Omron CX-Programmer project NewProject (CX-Programmer 9.11)

# PLC NewPLC1: CP1L M

## Global symbols (name address type ; comment)
AbsoluteActualPosition D0 DINT  ; Absolute Actual Position
ActualVelocity D2 DINT  ; Actual Velocity
A641.00 BOOL  ; $?St$Bk?_#[4] / Modbus-RTU Master Execution Bit / Turned ON: Execution Started / ON: Execution In Progress / OFF: Not Executed Or Execution completed.$?St$Bk?_#[4]
A641.01 BOOL  ; $?St$Bk?_#[5] / Modbus-RTU Master Execution Normal Flag / ON: Execution Normal / OFF: Execution Error Or Still In Progress$?St$Bk?_#[5]
A641.02 BOOL  ; $?St$Bk?_#[6] / Modbus-RTU Master Execution Error Flag / ON: Execution Error / OFF: Execution Normal Or Still In Progress$?St$Bk?_#[6]
D100 CHANNEL  ; Number Of Modbus Data Bytes
H0 CHANNEL  ; Input Status
H0.00 BOOL  ; Input 1
H0.01 BOOL  ; Input 2
H0.02 BOOL  ; Input 3
H0.03 BOOL  ; Input 4
H0.04 BOOL  ; Input 5
H0.05 BOOL  ; Input 6
H0.06 BOOL  ; Input 7
H0.07 BOOL  ; Input 8
H1 CHANNEL  ; Input Status
H10 CHANNEL  ; Output Status
H10.00 BOOL  ; Output 1
H10.01 BOOL  ; Output 2
H10.02 BOOL  ; Output 3
H10.03 BOOL  ; Output 4
H10.04 BOOL  ; Output 5
H10.05 BOOL  ; Output 6
H10.06 BOOL  ; Output 7
H10.07 BOOL  ; Output 8
H11 CHANNEL  ; Output Status
H11.08 BOOL  ; Output 9
H11.09 BOOL  ; Output 10
H11.10 BOOL  ; Output 11
H11.11 BOOL  ; Output 12
H11.12 BOOL  ; Output 13
H11.13 BOOL  ; Output 14
H11.14 BOOL  ; Output 15
H11.15 BOOL  ; Output 16
H1.08 BOOL  ; Input 9
H1.09 BOOL  ; Input 10
H1.10 BOOL  ; Input 11
H1.11 BOOL  ; Input 12
H1.12 BOOL  ; Input 13
H1.13 BOOL  ; Input 14
H1.14 BOOL  ; Input 15
H1.15 BOOL  ; Input 16
H20 CHANNEL  ; Fault / Status Flags
H20.00 BOOL  ; $?St$Bk?_#[7] / Counter-Clockwise Limit Active (No Fault) "L02"$?St$Bk?_#[7]
H20.01 BOOL  ; $?St$Bk?_#[8] / Drive Enabled Condition "E"$?St$Bk?_#[8]
H21 CHANNEL  ; Fault / Status Flags
H21.00 BOOL  ; $?St$Bk?_#[9] / Encoder Feedback / Commutation Fault "F07"$?St$Bk?_#[9]
H21.01 BOOL  ; $?St$Bk?_#[10] / Fatal PLC Fault "F98"$?St$Bk?_#[10]
H21.02 BOOL  ; $?St$Bk?_#[11] / Fatal Sequence Program Fault "F97"$?St$Bk?_#[11]
H21.03 BOOL  ; $?St$Bk?_#[12] / Phasing Fault (Non-Fatal) "F51"$?St$Bk?_#[12]
H21.04 BOOL  ; $?St$Bk?_#[13] / Drive Over-Current Fault (Non-Fatal) "F52"$?St$Bk?_#[13]
H21.05 BOOL  ; $?St$Bk?_#[14] / Motor Over-Current Fault (Non-Fatal) "F53"$?St$Bk?_#[14]
H21.06 BOOL  ; $?St$Bk?_#[15] / Bus Under-Voltage Fault (Non-Fatal) "F54"$?St$Bk?_#[15]
H21.07 BOOL  ; $?St$Bk?_#[16] / Maximum Following-Error Fault (Non-Fatal) "F55"$?St$Bk?_#[16]
H21.08 BOOL  ; $?St$Bk?_#[17] / Velocity Regulation Fault (Non-Fatal) "F56"$?St$Bk?_#[17]
H21.09 BOOL  ; $?St$Bk?_#[18] / Serial Communications Fault (Non-Fatal) "F57"$?St$Bk?_#[18]
H21.10 BOOL  ; $?St$Bk?_#[19] / Positive Travel Limit Fault (Non-Fatal) "FL1"$?St$Bk?_#[19]
H21.11 BOOL  ; $?St$Bk?_#[20] / Negative Travel Limit Fault (Non-Fatal) "FL2"$?St$Bk?_#[20]
H21.12 BOOL  ; $?St$Bk?_#[21] / Sequential Program Execution Fault (Non-Fatal) "F58"$?St$Bk?_#[21]
H21.13 BOOL  ; $?St$Bk?_#[22] / Drive Disabled Condition "d"$?St$Bk?_#[22]
H21.14 BOOL  ; $?St$Bk?_#[23] / Phasing In Progress "P"$?St$Bk?_#[23]
H21.15 BOOL  ; $?St$Bk?_#[24] / Clockwise Travel Limit Active (No Fault) "L01"$?St$Bk?_#[24]
H22 CHANNEL  ; Fault / Status Flags
H22.00 BOOL  ; $?St$Bk?_#[25] / Processor Fault "F00"$?St$Bk?_#[25]
H22.01 BOOL  ; $?St$Bk?_#[26] / Drive Not Configured "F99"$?St$Bk?_#[26]
H22.02 BOOL net:
$?St$Bk?_#[27]
Power Selection Switch Fault  ; F01$?St$Bk?_#[27]
H22.03 BOOL  ; $?St$Bk?_#[28] / Bridge Hardware Fault "F02"$?St$Bk?_#[28]
H22.04 BOOL  ; $?St$Bk?_#[29] / Current Feedback Fault "F03"$?St$Bk?_#[29]
H22.05 BOOL  ; $?St$Bk?_#[30] / Current Regulation Fault "F04"$?St$Bk?_#[30]
H22.06 BOOL  ; $?St$Bk?_#[31] / Drive Over-Temperature Fault "F05"$?St$Bk?_#[31]
H22.07 BOOL  ; $?St$Bk?_#[32] / Motor Over-Temperature Fault "F06"$?St$Bk?_#[32]
W0.00 BOOL  ; Run Program 1
W0.01 BOOL  ; Run Program 2
W10.00 BOOL  ; Input 1
W10.01 BOOL  ; Input 2
W10.02 BOOL  ; Input 3
W10.03 BOOL  ; Input 4
W10.04 BOOL  ; Input 5
W10.05 BOOL  ; Input 6
W10.06 BOOL  ; Input 7
W10.07 BOOL  ; Input 8
W10.08 BOOL  ; Input 9
W10.09 BOOL  ; Input 10
W10.10 BOOL  ; Input 11
W10.11 BOOL  ; Input 12
W10.12 BOOL  ; Input 13
W10.13 BOOL  ; Input 14
W10.14 BOOL  ; Input 15
W10.15 BOOL  ; Input 16
W1.00 BOOL  ; Read Inputs
W1.01 BOOL  ; Read Outputs
W20.00 BOOL  ; Output 1
W20.01 BOOL  ; Output 2
W20.02 BOOL  ; Output 3
W20.03 BOOL  ; Output 4
W20.04 BOOL  ; Output 5
W20.05 BOOL  ; Output 6
W20.06 BOOL  ; Output 7
W20.07 BOOL  ; Output 8
W20.08 BOOL  ; Output 9
W20.09 BOOL  ; Output 10
W20.10 BOOL  ; Output 11
W20.11 BOOL  ; Output 12
W20.12 BOOL  ; Output 13
W20.13 BOOL  ; Output 14
W20.14 BOOL  ; Output 15
W20.15 BOOL  ; Output 16
W21.00 BOOL  ; $?St$Bk?_#[33] / Encoder Feedback / Commutation Fault "F07"$?St$Bk?_#[33]
W21.01 BOOL  ; $?St$Bk?_#[34] / Fatal PLC Fault "F98"$?St$Bk?_#[34]
W21.02 BOOL  ; $?St$Bk?_#[35] / Fatal Sequence Program Fault "F97"$?St$Bk?_#[35]
W21.03 BOOL  ; $?St$Bk?_#[36] / Phasing Fault (Non-Fatal) "F51"$?St$Bk?_#[36]
W21.04 BOOL  ; $?St$Bk?_#[37] / Drive Over-Current Fault (Non-Fatal) "F52"$?St$Bk?_#[37]
W21.05 BOOL  ; $?St$Bk?_#[38] / Motor Over-Current Fault (Non-Fatal) "F53"$?St$Bk?_#[38]
W21.06 BOOL  ; $?St$Bk?_#[39] / Bus Under-Voltage Fault (Non-Fatal) "F54"$?St$Bk?_#[39]
W21.07 BOOL  ; $?St$Bk?_#[40] / Maximum Following-Error Fault (Non-Fatal) "F55"$?St$Bk?_#[40]
W21.08 BOOL  ; $?St$Bk?_#[41] / Velocity Regulation Fault (Non-Fatal) "F56"$?St$Bk?_#[41]
W21.09 BOOL  ; $?St$Bk?_#[42] / Serial Communications Fault (Non-Fatal) "F57"$?St$Bk?_#[42]
W21.10 BOOL  ; $?St$Bk?_#[43] / Positive Travel Limit Fault (Non-Fatal) "FL1"$?St$Bk?_#[43]
W21.11 BOOL  ; $?St$Bk?_#[44] / Negative Travel Limit Fault (Non-Fatal) "FL2"$?St$Bk?_#[44]
W21.12 BOOL  ; $?St$Bk?_#[45] / Sequential Program Execution Fault (Non-Fatal) "F58"$?St$Bk?_#[45]
W21.13 BOOL  ; $?St$Bk?_#[46] / Drive Disabled Condition "d"$?St$Bk?_#[46]
W21.14 BOOL  ; $?St$Bk?_#[47] / Phasing In Progress "P"$?St$Bk?_#[47]
W21.15 BOOL  ; $?St$Bk?_#[48] / Clockwise Travel Limit Active (No Fault) "L01"$?St$Bk?_#[48]
W22.00 BOOL  ; $?St$Bk?_#[49] / Processor Fault "F00"$?St$Bk?_#[49]
W22.01 BOOL  ; $?St$Bk?_#[50] / Drive Not Configured "F99"$?St$Bk?_#[50]
W22.02 BOOL net:
$?St$Bk?_#[51]
Power Selection Switch Fault  ; F01$?St$Bk?_#[51]
W22.03 BOOL  ; $?St$Bk?_#[52] / Bridge Hardware Fault "F02"$?St$Bk?_#[52]
W22.04 BOOL  ; $?St$Bk?_#[53] / Current Feedback Fault "F03"$?St$Bk?_#[53]
W22.05 BOOL  ; $?St$Bk?_#[54] / Current Regulation Fault "F04"$?St$Bk?_#[54]
W22.06 BOOL  ; $?St$Bk?_#[55] / Drive Over-Temperature Fault "F05"$?St$Bk?_#[55]
W22.07 BOOL  ; $?St$Bk?_#[56] / Motor Over-Temperature Fault "F06"$?St$Bk?_#[56]
W2.00 BOOL  ; Read Absolute Actual Position
W2.01 BOOL  ; Read Actual Velocity
W2.02 BOOL  ; Read Torque Output
W30.00 BOOL  ; $?St$Bk?_#[57] / Counter-Clockwise Limit Active (No Fault) "L02"$?St$Bk?_#[57]
W30.01 BOOL  ; $?St$Bk?_#[58] / Drive Enabled Condition "E"$?St$Bk?_#[58]
W3.00 BOOL  ; Preset Actual Position
W3.01 BOOL  ; Preset Actual Velocity
W4.00 BOOL  ; Report Slave ID
CommandCommunicationsDataWord1 D32203 CHANNEL  ; Command Communications Data - Word 1 (94 Bytes Maximum)
CommandCommunicationsDataWord2 D32204 CHANNEL  ; Command Communications Data - Word 2 (94 Bytes Maximum)
CommandCommunicationsDataWord3 D32205 CHANNEL  ; Command Communications Data - Word 3 (94 Bytes Maximum)
CommandCommunicationsDataWord4 D32206 CHANNEL  ; Command Communications Data - Word 4 (94 Bytes Maximum)
CommandCommunicationsDataWord5 D32207 CHANNEL  ; Command Communications Data - Word 5 (94 Bytes Maximum)
CommandFunctionCode D32201 CHANNEL  ; $?St$Bk?_#[59] / Command Function Code / Bits 0-7 (*8-15 = 00)$?St$Bk?_#[59]
CommandNumberOfCommunicationBytes D32202 CHANNEL  ; Command Number Of Communications Data Bytes (0000 To 005E HEX)
CommandSlaveAddress D32200 CHANNEL  ; $?St$Bk?_#[60] / Command Slave Address (00 To F7 HEX) / Bits 0-7 (*8-15 = 00)$?St$Bk?_#[60]
RAM_PositionRegister PresetRegister
RAM_RegisterValue D10 DINT  ; RAM Register Value
RAM_VelocityRegister PresetRegister
ReadAbsoluteActualPosition ReadHoldingRegister
ReadActualTorque ReadHoldingRegister
ReadActualVelocity ReadHoldingRegister
ReadInputs ReadInputStatus
ReadOutputs ReadOutputStatus
ResponseCommunicationDataWord1 D32254 CHANNEL  ; Response Communications Data - Word 1 (92 Bytes Maximum)
ResponseCommunicationsDataWord2 D32255 CHANNEL  ; Response Communcations Data - Word 2 (92 Bytes Maximum)
ResponseCommunicationsDataWord3 D32256 CHANNEL  ; Response Communications Data - Word 3 (92 Bytes Maximum)
ResponseCommunicationsDataWord4 D32257 CHANNEL  ; Response Communications Data - Word 4 (92 Bytes Maximum)
ResponseCommunicationsDataWord5 D32258 CHANNEL  ; Response Communications Data - Word 5 (92 Bytes Maximum)
ResponseErrorCode D32252 CHANNEL  ; $?St$Bk?_#[61] / Response Error Code / Bits 0-7 (*8-15 = 00)$?St$Bk?_#[61]
ResponseFunctionCode D32251 CHANNEL  ; $?St$Bk?_#[62] / Response Function Code / Bits 0-7 (*8-15 = 00)$?St$Bk?_#[62]
ResponseNumberOfCommunicationBytes D32253 CHANNEL  ; Response Number Of Response Data Bytes (0000 To 03EA HEX)
ResponseSlaveAddress D32250 CHANNEL  ; $?St$Bk?_#[63] / Response Slave Address (00 To F7 HEX) / Bits 0-7 (*8-15 = 00)$?St$Bk?_#[63]
RunProgram1 ForceSingleCoil
RunProgram2 ForceSingleCoil
StopProgram1 ForceSingleCoil
StopProgram2 ForceSingleCoil
TorqueOutput D4 DINT  ; Torque Output

## Program NewProgram1 (cyclic task 0)
; ***SIMPLE MODBUS Communications:  CP1L-M Serial Port 1 To Axiom Plus PV10 / Reference CP1L Operation Manual Section 6-3-3 (W462) & Axiom Plus PV Series User Manual Chapter 13 (3600-4628) & Modicon Modbus Protocol Reference Guide (PI–MBUS–300) / 01 Read Coil Status / 02 Read Input Status / 03 Read Holding Registers / 05 Force Single Coil / 15 Force Multiple Coils / 16 Preset Multiple Registers / 17 Report Slave ID

### Section ModbusCommands

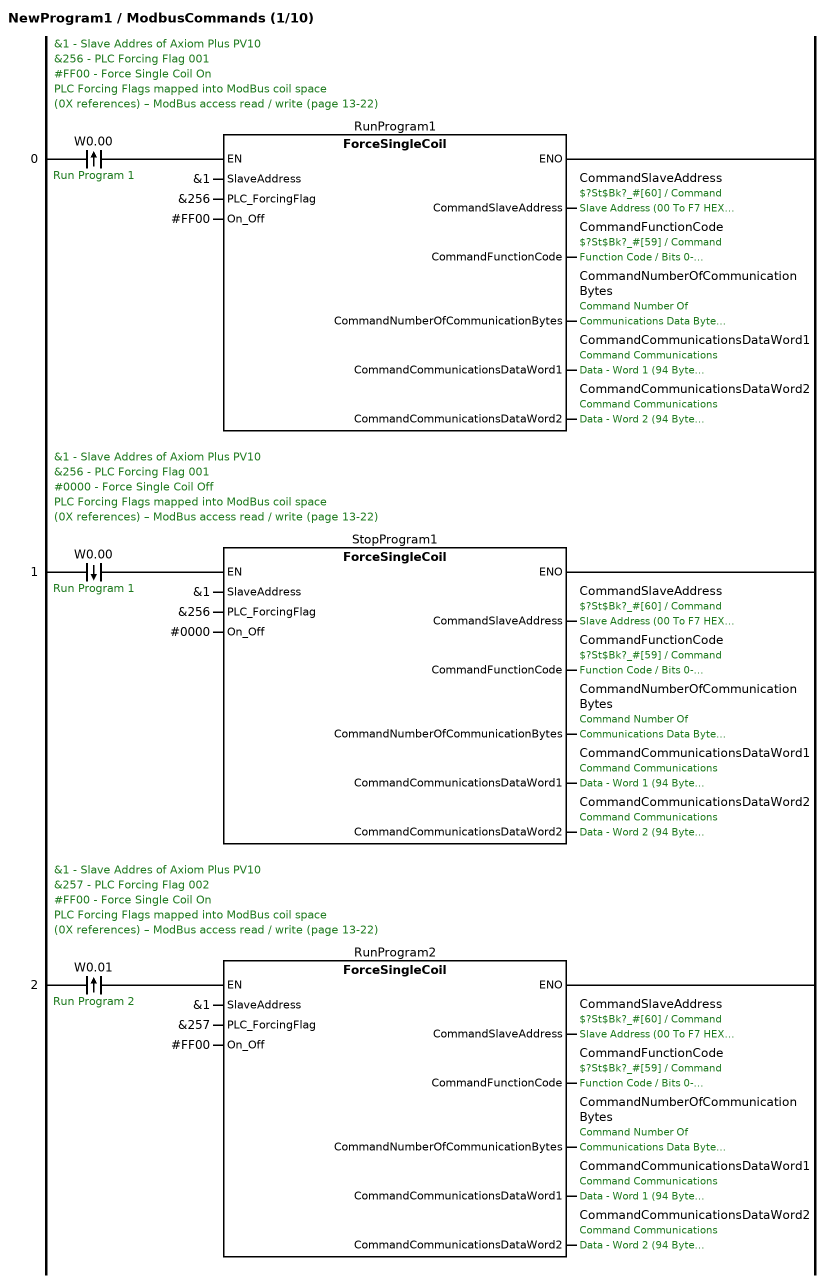
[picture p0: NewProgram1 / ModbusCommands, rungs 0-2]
; rung 0: &1 - Slave Addres of Axiom Plus PV10 / &256 - PLC Forcing Flag 001 / #FF00 - Force Single Coil On / PLC Forcing Flags mapped into ModBus coil space / (0X references) – ModBus access read / write (page 13-22)
@LD W0.00  ; Run Program 1
CALL RunProgram1 : ForceSingleCoil (SlaveAddress := &1, PLC_ForcingFlag := &256, On_Off := #FF00, CommandSlaveAddress => CommandSlaveAddress, CommandFunctionCode => CommandFunctionCode, CommandNumberOfCommunicationBytes => CommandNumberOfCommunicationBytes, CommandCommunicationsDataWord1 => CommandCommunicationsDataWord1, CommandCommunicationsDataWord2 => CommandCommunicationsDataWord2)  ; $?St$Bk?_#[60] / Command Slave Address (00 To F7 HEX) / Bits 0-7 (*8-15 = 00)$?St$Bk?_#[60], $?St$Bk?_#[59] / Command Function Code / Bits 0-7 (*8-15 = 00)$?St$Bk?_#[59], Command Number Of Communications Data Bytes (0000 To 005E HEX), Command Communications Data - Word 1 (94 Bytes Maximum), Command Communications Data - Word 2 (94 Bytes Maximum)
; rung 1: &1 - Slave Addres of Axiom Plus PV10 / &256 - PLC Forcing Flag 001 / #0000 - Force Single Coil Off / PLC Forcing Flags mapped into ModBus coil space / (0X references) – ModBus access read / write (page 13-22)
%LD W0.00  ; Run Program 1
CALL StopProgram1 : ForceSingleCoil (SlaveAddress := &1, PLC_ForcingFlag := &256, On_Off := #0000, CommandSlaveAddress => CommandSlaveAddress, CommandFunctionCode => CommandFunctionCode, CommandNumberOfCommunicationBytes => CommandNumberOfCommunicationBytes, CommandCommunicationsDataWord1 => CommandCommunicationsDataWord1, CommandCommunicationsDataWord2 => CommandCommunicationsDataWord2)  ; $?St$Bk?_#[60] / Command Slave Address (00 To F7 HEX) / Bits 0-7 (*8-15 = 00)$?St$Bk?_#[60], $?St$Bk?_#[59] / Command Function Code / Bits 0-7 (*8-15 = 00)$?St$Bk?_#[59], Command Number Of Communications Data Bytes (0000 To 005E HEX), Command Communications Data - Word 1 (94 Bytes Maximum), Command Communications Data - Word 2 (94 Bytes Maximum)
; rung 2: &1 - Slave Addres of Axiom Plus PV10 / &257 - PLC Forcing Flag 002 / #FF00 - Force Single Coil On / PLC Forcing Flags mapped into ModBus coil space / (0X references) – ModBus access read / write (page 13-22)
@LD W0.01  ; Run Program 2
CALL RunProgram2 : ForceSingleCoil (SlaveAddress := &1, PLC_ForcingFlag := &257, On_Off := #FF00, CommandSlaveAddress => CommandSlaveAddress, CommandFunctionCode => CommandFunctionCode, CommandNumberOfCommunicationBytes => CommandNumberOfCommunicationBytes, CommandCommunicationsDataWord1 => CommandCommunicationsDataWord1, CommandCommunicationsDataWord2 => CommandCommunicationsDataWord2)  ; $?St$Bk?_#[60] / Command Slave Address (00 To F7 HEX) / Bits 0-7 (*8-15 = 00)$?St$Bk?_#[60], $?St$Bk?_#[59] / Command Function Code / Bits 0-7 (*8-15 = 00)$?St$Bk?_#[59], Command Number Of Communications Data Bytes (0000 To 005E HEX), Command Communications Data - Word 1 (94 Bytes Maximum), Command Communications Data - Word 2 (94 Bytes Maximum)

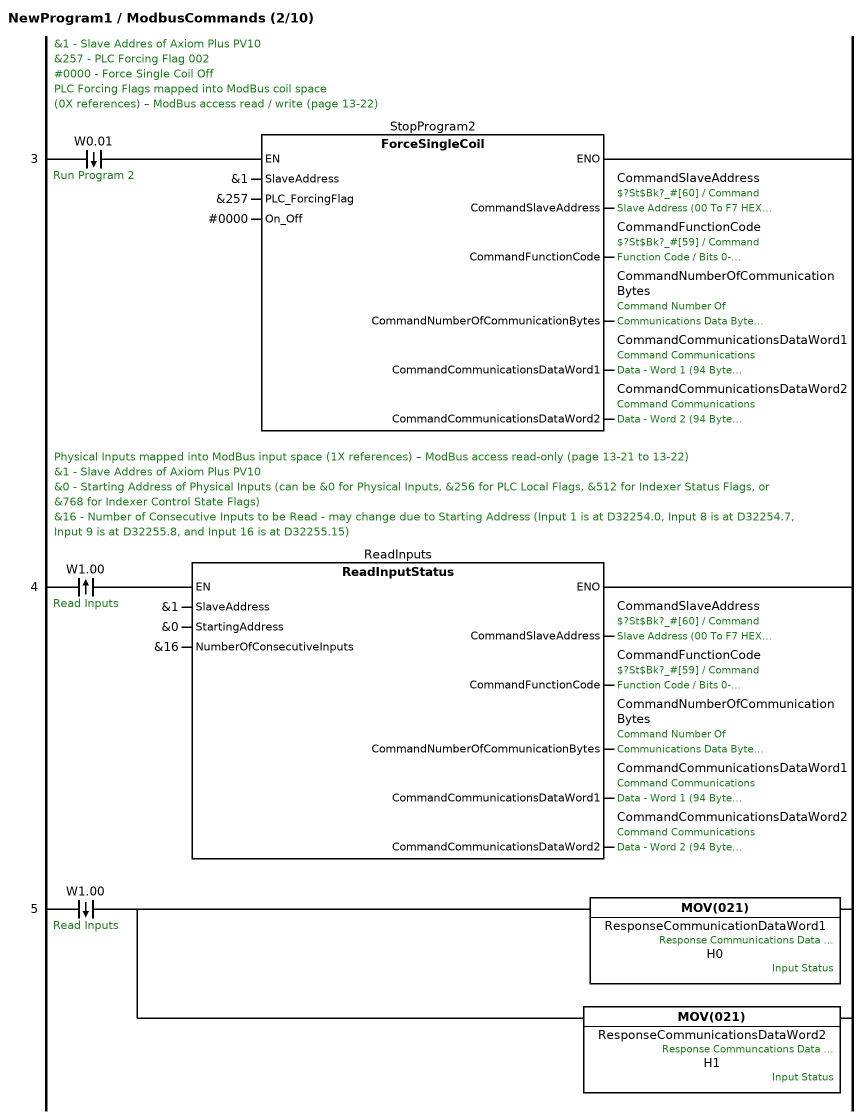
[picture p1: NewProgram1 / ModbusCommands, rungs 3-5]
; rung 3: &1 - Slave Addres of Axiom Plus PV10 / &257 - PLC Forcing Flag 002 / #0000 - Force Single Coil Off / PLC Forcing Flags mapped into ModBus coil space / (0X references) – ModBus access read / write (page 13-22)
%LD W0.01  ; Run Program 2
CALL StopProgram2 : ForceSingleCoil (SlaveAddress := &1, PLC_ForcingFlag := &257, On_Off := #0000, CommandSlaveAddress => CommandSlaveAddress, CommandFunctionCode => CommandFunctionCode, CommandNumberOfCommunicationBytes => CommandNumberOfCommunicationBytes, CommandCommunicationsDataWord1 => CommandCommunicationsDataWord1, CommandCommunicationsDataWord2 => CommandCommunicationsDataWord2)  ; $?St$Bk?_#[60] / Command Slave Address (00 To F7 HEX) / Bits 0-7 (*8-15 = 00)$?St$Bk?_#[60], $?St$Bk?_#[59] / Command Function Code / Bits 0-7 (*8-15 = 00)$?St$Bk?_#[59], Command Number Of Communications Data Bytes (0000 To 005E HEX), Command Communications Data - Word 1 (94 Bytes Maximum), Command Communications Data - Word 2 (94 Bytes Maximum)
; rung 4: Physical Inputs mapped into ModBus input space (1X references) – ModBus access read-only (page 13-21 to 13-22) / &1 - Slave Addres of Axiom Plus PV10 / &0 - Starting Address of Physical Inputs (can be &0 for Physical Inputs, &256 for PLC Local Flags, &512 for Indexer Status Flags, or &768 for Indexer Control State Flags) / &16 - Number of Consecutive Inputs to be Read - may change due to Starting Address (Input 1 is at D32254.0, Input 8 is at D32254.7, Input 9 is at D32255.8, and Input 16 is at D32255.15)
@LD W1.00  ; Read Inputs
CALL ReadInputs : ReadInputStatus (SlaveAddress := &1, StartingAddress := &0, NumberOfConsecutiveInputs := &16, CommandSlaveAddress => CommandSlaveAddress, CommandFunctionCode => CommandFunctionCode, CommandNumberOfCommunicationBytes => CommandNumberOfCommunicationBytes, CommandCommunicationsDataWord1 => CommandCommunicationsDataWord1, CommandCommunicationsDataWord2 => CommandCommunicationsDataWord2)  ; $?St$Bk?_#[60] / Command Slave Address (00 To F7 HEX) / Bits 0-7 (*8-15 = 00)$?St$Bk?_#[60], $?St$Bk?_#[59] / Command Function Code / Bits 0-7 (*8-15 = 00)$?St$Bk?_#[59], Command Number Of Communications Data Bytes (0000 To 005E HEX), Command Communications Data - Word 1 (94 Bytes Maximum), Command Communications Data - Word 2 (94 Bytes Maximum)
; rung 5
%LD W1.00  ; Read Inputs
MOV(021) ResponseCommunicationDataWord1 H0  ; Response Communications Data - Word 1 (92 Bytes Maximum), Input Status
MOV(021) ResponseCommunicationsDataWord2 H1  ; Response Communcations Data - Word 2 (92 Bytes Maximum), Input Status

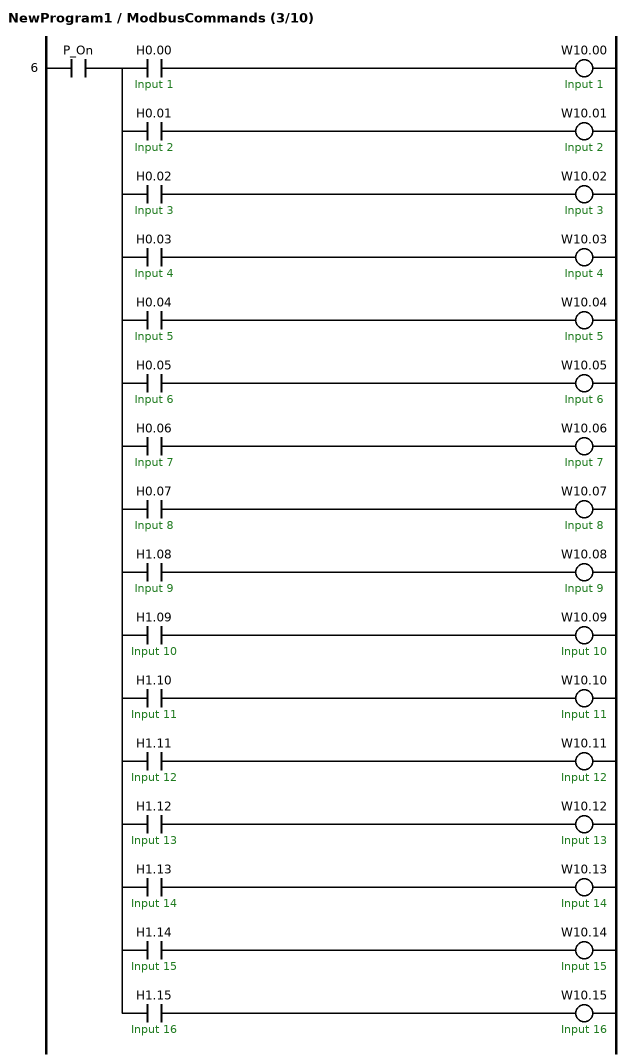
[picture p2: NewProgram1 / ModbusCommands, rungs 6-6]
; rung 6
LD P_On
OUT TR0
AND H0.00  ; Input 1
OUT W10.00  ; Input 1
LD TR0
AND H0.01  ; Input 2
OUT W10.01  ; Input 2
LD TR0
AND H0.02  ; Input 3
OUT W10.02  ; Input 3
LD TR0
AND H0.03  ; Input 4
OUT W10.03  ; Input 4
LD TR0
AND H0.04  ; Input 5
OUT W10.04  ; Input 5
LD TR0
AND H0.05  ; Input 6
OUT W10.05  ; Input 6
LD TR0
AND H0.06  ; Input 7
OUT W10.06  ; Input 7
LD TR0
AND H0.07  ; Input 8
OUT W10.07  ; Input 8
LD TR0
AND H1.08  ; Input 9
OUT W10.08  ; Input 9
LD TR0
AND H1.09  ; Input 10
OUT W10.09  ; Input 10
LD TR0
AND H1.10  ; Input 11
OUT W10.10  ; Input 11
LD TR0
AND H1.11  ; Input 12
OUT W10.11  ; Input 12
LD TR0
AND H1.12  ; Input 13
OUT W10.12  ; Input 13
LD TR0
AND H1.13  ; Input 14
OUT W10.13  ; Input 14
LD TR0
AND H1.14  ; Input 15
OUT W10.14  ; Input 15
LD TR0
AND H1.15  ; Input 16
OUT W10.15  ; Input 16

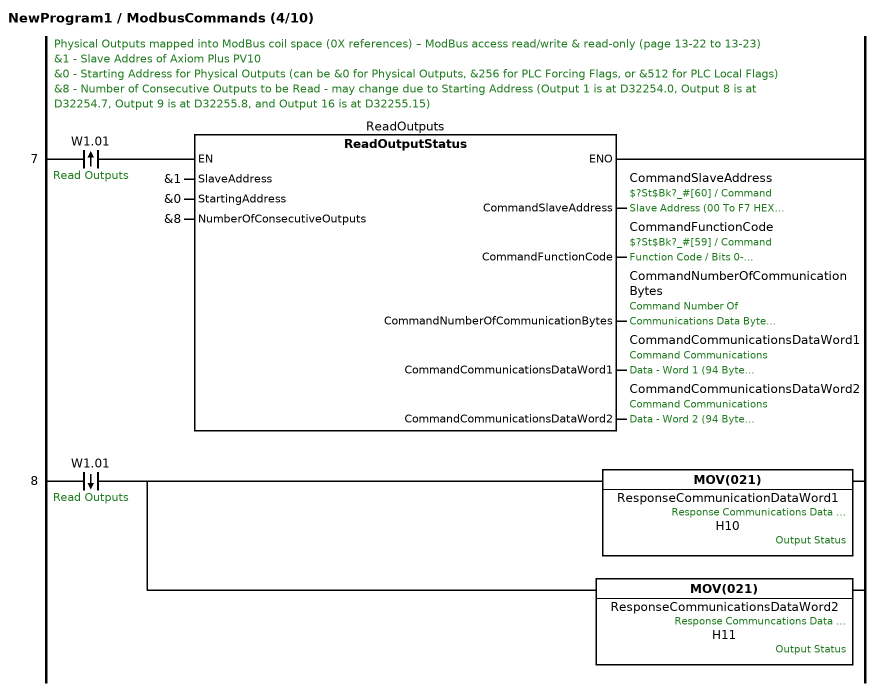
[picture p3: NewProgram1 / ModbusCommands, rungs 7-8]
; rung 7: Physical Outputs mapped into ModBus coil space (0X references) – ModBus access read/write & read-only (page 13-22 to 13-23) / &1 - Slave Addres of Axiom Plus PV10 / &0 - Starting Address for Physical Outputs (can be &0 for Physical Outputs, &256 for PLC Forcing Flags, or &512 for PLC Local Flags) / &8 - Number of Consecutive Outputs to be Read - may change due to Starting Address (Output 1 is at D32254.0, Output 8 is at D32254.7, Output 9 is at D32255.8, and Output 16 is at D32255.15)
@LD W1.01  ; Read Outputs
CALL ReadOutputs : ReadOutputStatus (SlaveAddress := &1, StartingAddress := &0, NumberOfConsecutiveOutputs := &8, CommandSlaveAddress => CommandSlaveAddress, CommandFunctionCode => CommandFunctionCode, CommandNumberOfCommunicationBytes => CommandNumberOfCommunicationBytes, CommandCommunicationsDataWord1 => CommandCommunicationsDataWord1, CommandCommunicationsDataWord2 => CommandCommunicationsDataWord2)  ; $?St$Bk?_#[60] / Command Slave Address (00 To F7 HEX) / Bits 0-7 (*8-15 = 00)$?St$Bk?_#[60], $?St$Bk?_#[59] / Command Function Code / Bits 0-7 (*8-15 = 00)$?St$Bk?_#[59], Command Number Of Communications Data Bytes (0000 To 005E HEX), Command Communications Data - Word 1 (94 Bytes Maximum), Command Communications Data - Word 2 (94 Bytes Maximum)
; rung 8
%LD W1.01  ; Read Outputs
MOV(021) ResponseCommunicationDataWord1 H10  ; Response Communications Data - Word 1 (92 Bytes Maximum), Output Status
MOV(021) ResponseCommunicationsDataWord2 H11  ; Response Communcations Data - Word 2 (92 Bytes Maximum), Output Status

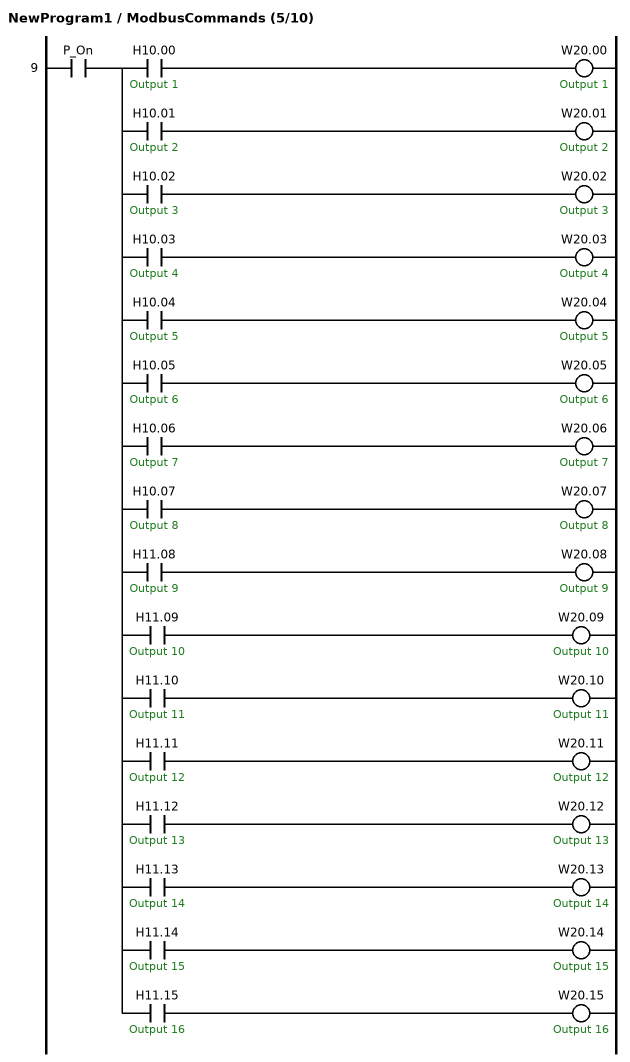
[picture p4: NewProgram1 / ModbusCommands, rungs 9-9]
; rung 9
LD P_On
OUT TR0
AND H10.00  ; Output 1
OUT W20.00  ; Output 1
LD TR0
AND H10.01  ; Output 2
OUT W20.01  ; Output 2
LD TR0
AND H10.02  ; Output 3
OUT W20.02  ; Output 3
LD TR0
AND H10.03  ; Output 4
OUT W20.03  ; Output 4
LD TR0
AND H10.04  ; Output 5
OUT W20.04  ; Output 5
LD TR0
AND H10.05  ; Output 6
OUT W20.05  ; Output 6
LD TR0
AND H10.06  ; Output 7
OUT W20.06  ; Output 7
LD TR0
AND H10.07  ; Output 8
OUT W20.07  ; Output 8
LD TR0
AND H11.08  ; Output 9
OUT W20.08  ; Output 9
LD TR0
AND H11.09  ; Output 10
OUT W20.09  ; Output 10
LD TR0
AND H11.10  ; Output 11
OUT W20.10  ; Output 11
LD TR0
AND H11.11  ; Output 12
OUT W20.11  ; Output 12
LD TR0
AND H11.12  ; Output 13
OUT W20.12  ; Output 13
LD TR0
AND H11.13  ; Output 14
OUT W20.13  ; Output 14
LD TR0
AND H11.14  ; Output 15
OUT W20.14  ; Output 15
LD TR0
AND H11.15  ; Output 16
OUT W20.15  ; Output 16

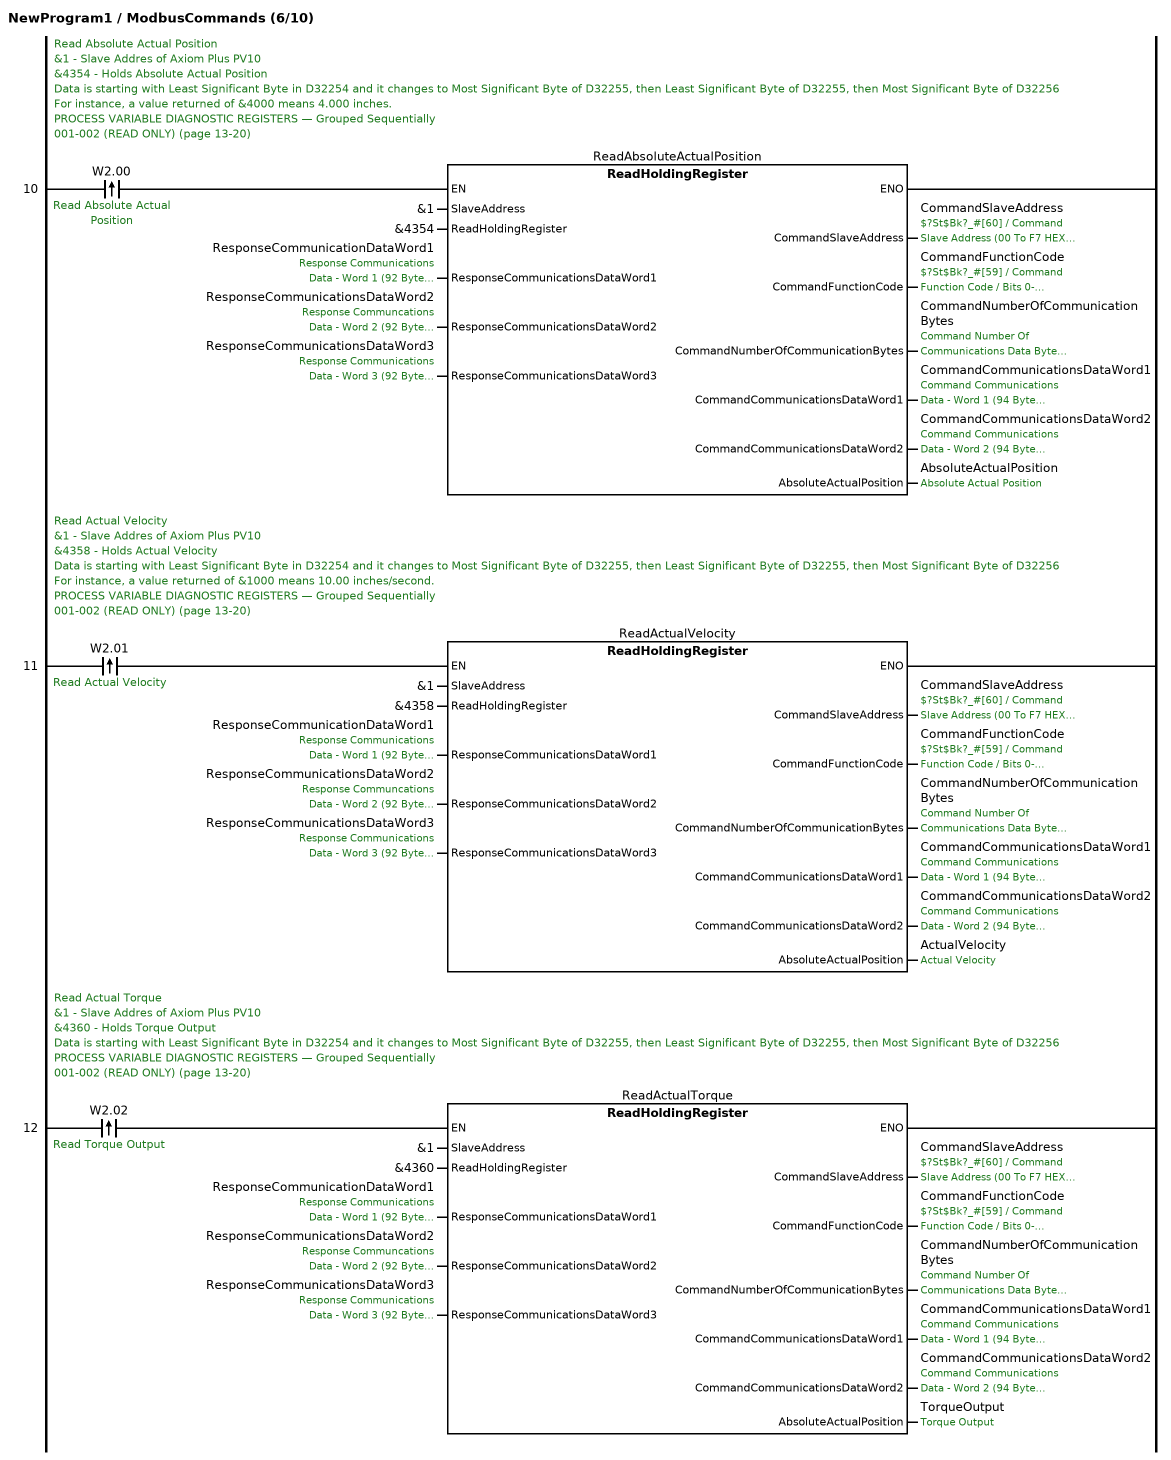
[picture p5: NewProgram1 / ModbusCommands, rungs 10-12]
; rung 10: Read Absolute Actual Position / &1 - Slave Addres of Axiom Plus PV10 / &4354 - Holds Absolute Actual Position / Data is starting with Least Significant Byte in D32254 and it changes to Most Significant Byte of D32255, then Least Significant Byte of D32255, then Most Significant Byte of D32256 / For instance, a value returned of &4000 means 4.000 inches. / PROCESS VARIABLE DIAGNOSTIC REGISTERS — Grouped Sequentially / 001-002 (READ ONLY) (page 13-20)
@LD W2.00  ; Read Absolute Actual Position
CALL ReadAbsoluteActualPosition : ReadHoldingRegister (SlaveAddress := &1, ReadHoldingRegister := &4354, ResponseCommunicationsDataWord1 := ResponseCommunicationDataWord1, ResponseCommunicationsDataWord2 := ResponseCommunicationsDataWord2, ResponseCommunicationsDataWord3 := ResponseCommunicationsDataWord3, CommandSlaveAddress => CommandSlaveAddress, CommandFunctionCode => CommandFunctionCode, CommandNumberOfCommunicationBytes => CommandNumberOfCommunicationBytes, CommandCommunicationsDataWord1 => CommandCommunicationsDataWord1, CommandCommunicationsDataWord2 => CommandCommunicationsDataWord2, AbsoluteActualPosition => AbsoluteActualPosition)  ; Response Communications Data - Word 1 (92 Bytes Maximum), Response Communcations Data - Word 2 (92 Bytes Maximum), Response Communications Data - Word 3 (92 Bytes Maximum), $?St$Bk?_#[60] / Command Slave Address (00 To F7 HEX) / Bits 0-7 (*8-15 = 00)$?St$Bk?_#[60], $?St$Bk?_#[59] / Command Function Code / Bits 0-7 (*8-15 = 00)$?St$Bk?_#[59], Command Number Of Communications Data Bytes (0000 To 005E HEX), Command Communications Data - Word 1 (94 Bytes Maximum), Command Communications Data - Word 2 (94 Bytes Maximum), Absolute Actual Position
; rung 11: Read Actual Velocity / &1 - Slave Addres of Axiom Plus PV10 / &4358 - Holds Actual Velocity / Data is starting with Least Significant Byte in D32254 and it changes to Most Significant Byte of D32255, then Least Significant Byte of D32255, then Most Significant Byte of D32256 / For instance, a value returned of &1000 means 10.00 inches/second. / PROCESS VARIABLE DIAGNOSTIC REGISTERS — Grouped Sequentially / 001-002 (READ ONLY) (page 13-20)
@LD W2.01  ; Read Actual Velocity
CALL ReadActualVelocity : ReadHoldingRegister (SlaveAddress := &1, ReadHoldingRegister := &4358, ResponseCommunicationsDataWord1 := ResponseCommunicationDataWord1, ResponseCommunicationsDataWord2 := ResponseCommunicationsDataWord2, ResponseCommunicationsDataWord3 := ResponseCommunicationsDataWord3, CommandSlaveAddress => CommandSlaveAddress, CommandFunctionCode => CommandFunctionCode, CommandNumberOfCommunicationBytes => CommandNumberOfCommunicationBytes, CommandCommunicationsDataWord1 => CommandCommunicationsDataWord1, CommandCommunicationsDataWord2 => CommandCommunicationsDataWord2, AbsoluteActualPosition => ActualVelocity)  ; Response Communications Data - Word 1 (92 Bytes Maximum), Response Communcations Data - Word 2 (92 Bytes Maximum), Response Communications Data - Word 3 (92 Bytes Maximum), $?St$Bk?_#[60] / Command Slave Address (00 To F7 HEX) / Bits 0-7 (*8-15 = 00)$?St$Bk?_#[60], $?St$Bk?_#[59] / Command Function Code / Bits 0-7 (*8-15 = 00)$?St$Bk?_#[59], Command Number Of Communications Data Bytes (0000 To 005E HEX), Command Communications Data - Word 1 (94 Bytes Maximum), Command Communications Data - Word 2 (94 Bytes Maximum), Actual Velocity
; rung 12: Read Actual Torque / &1 - Slave Addres of Axiom Plus PV10 / &4360 - Holds Torque Output / Data is starting with Least Significant Byte in D32254 and it changes to Most Significant Byte of D32255, then Least Significant Byte of D32255, then Most Significant Byte of D32256 / PROCESS VARIABLE DIAGNOSTIC REGISTERS — Grouped Sequentially / 001-002 (READ ONLY) (page 13-20)
@LD W2.02  ; Read Torque Output
CALL ReadActualTorque : ReadHoldingRegister (SlaveAddress := &1, ReadHoldingRegister := &4360, ResponseCommunicationsDataWord1 := ResponseCommunicationDataWord1, ResponseCommunicationsDataWord2 := ResponseCommunicationsDataWord2, ResponseCommunicationsDataWord3 := ResponseCommunicationsDataWord3, CommandSlaveAddress => CommandSlaveAddress, CommandFunctionCode => CommandFunctionCode, CommandNumberOfCommunicationBytes => CommandNumberOfCommunicationBytes, CommandCommunicationsDataWord1 => CommandCommunicationsDataWord1, CommandCommunicationsDataWord2 => CommandCommunicationsDataWord2, AbsoluteActualPosition => TorqueOutput)  ; Response Communications Data - Word 1 (92 Bytes Maximum), Response Communcations Data - Word 2 (92 Bytes Maximum), Response Communications Data - Word 3 (92 Bytes Maximum), $?St$Bk?_#[60] / Command Slave Address (00 To F7 HEX) / Bits 0-7 (*8-15 = 00)$?St$Bk?_#[60], $?St$Bk?_#[59] / Command Function Code / Bits 0-7 (*8-15 = 00)$?St$Bk?_#[59], Command Number Of Communications Data Bytes (0000 To 005E HEX), Command Communications Data - Word 1 (94 Bytes Maximum), Command Communications Data - Word 2 (94 Bytes Maximum), Torque Output

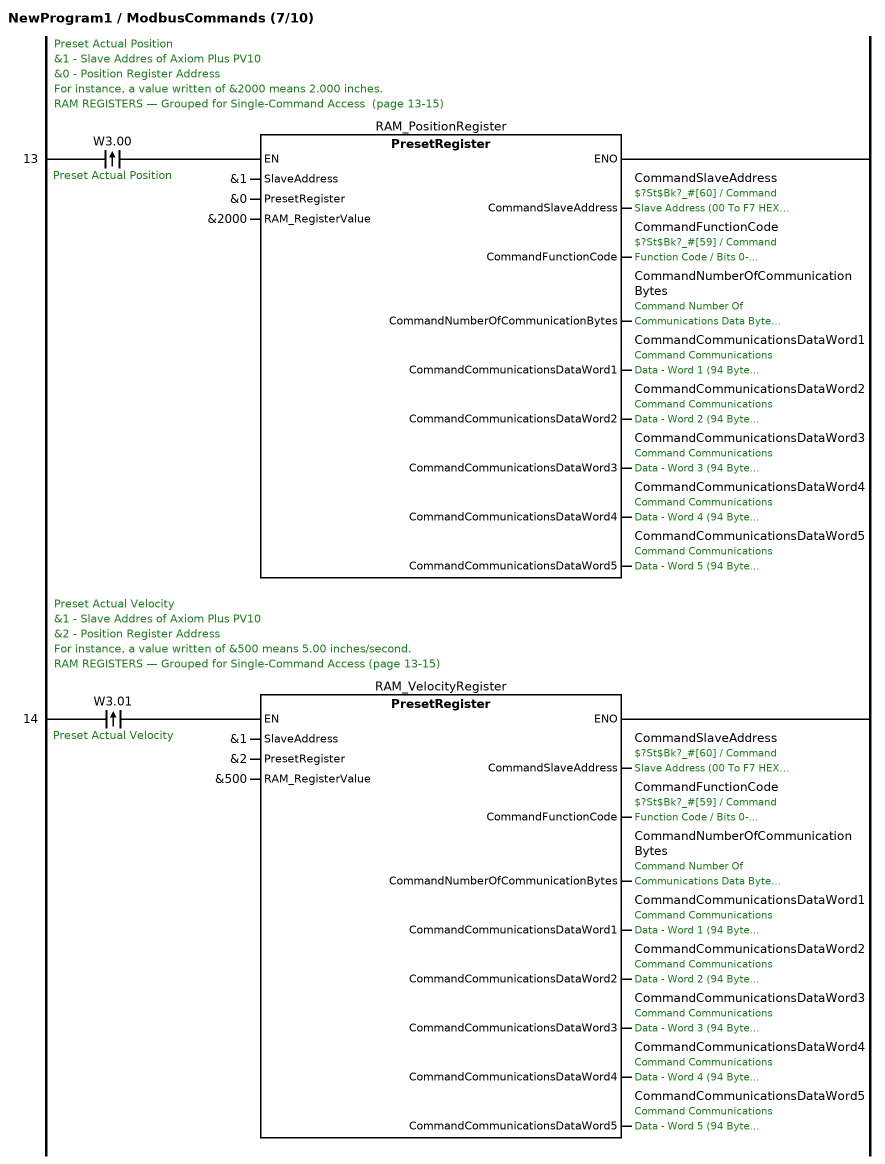
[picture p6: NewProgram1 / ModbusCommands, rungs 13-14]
; rung 13: Preset Actual Position / &1 - Slave Addres of Axiom Plus PV10 / &0 - Position Register Address / For instance, a value written of &2000 means 2.000 inches. / RAM REGISTERS — Grouped for Single-Command Access  (page 13-15)
@LD W3.00  ; Preset Actual Position
CALL RAM_PositionRegister : PresetRegister (SlaveAddress := &1, PresetRegister := &0, RAM_RegisterValue := &2000, CommandSlaveAddress => CommandSlaveAddress, CommandFunctionCode => CommandFunctionCode, CommandNumberOfCommunicationBytes => CommandNumberOfCommunicationBytes, CommandCommunicationsDataWord1 => CommandCommunicationsDataWord1, CommandCommunicationsDataWord2 => CommandCommunicationsDataWord2, CommandCommunicationsDataWord3 => CommandCommunicationsDataWord3, CommandCommunicationsDataWord4 => CommandCommunicationsDataWord4, CommandCommunicationsDataWord5 => CommandCommunicationsDataWord5)  ; $?St$Bk?_#[60] / Command Slave Address (00 To F7 HEX) / Bits 0-7 (*8-15 = 00)$?St$Bk?_#[60], $?St$Bk?_#[59] / Command Function Code / Bits 0-7 (*8-15 = 00)$?St$Bk?_#[59], Command Number Of Communications Data Bytes (0000 To 005E HEX), Command Communications Data - Word 1 (94 Bytes Maximum), Command Communications Data - Word 2 (94 Bytes Maximum), Command Communications Data - Word 3 (94 Bytes Maximum), Command Communications Data - Word 4 (94 Bytes Maximum), Command Communications Data - Word 5 (94 Bytes Maximum)
; rung 14: Preset Actual Velocity / &1 - Slave Addres of Axiom Plus PV10 / &2 - Position Register Address / For instance, a value written of &500 means 5.00 inches/second. / RAM REGISTERS — Grouped for Single-Command Access (page 13-15)
@LD W3.01  ; Preset Actual Velocity
CALL RAM_VelocityRegister : PresetRegister (SlaveAddress := &1, PresetRegister := &2, RAM_RegisterValue := &500, CommandSlaveAddress => CommandSlaveAddress, CommandFunctionCode => CommandFunctionCode, CommandNumberOfCommunicationBytes => CommandNumberOfCommunicationBytes, CommandCommunicationsDataWord1 => CommandCommunicationsDataWord1, CommandCommunicationsDataWord2 => CommandCommunicationsDataWord2, CommandCommunicationsDataWord3 => CommandCommunicationsDataWord3, CommandCommunicationsDataWord4 => CommandCommunicationsDataWord4, CommandCommunicationsDataWord5 => CommandCommunicationsDataWord5)  ; $?St$Bk?_#[60] / Command Slave Address (00 To F7 HEX) / Bits 0-7 (*8-15 = 00)$?St$Bk?_#[60], $?St$Bk?_#[59] / Command Function Code / Bits 0-7 (*8-15 = 00)$?St$Bk?_#[59], Command Number Of Communications Data Bytes (0000 To 005E HEX), Command Communications Data - Word 1 (94 Bytes Maximum), Command Communications Data - Word 2 (94 Bytes Maximum), Command Communications Data - Word 3 (94 Bytes Maximum), Command Communications Data - Word 4 (94 Bytes Maximum), Command Communications Data - Word 5 (94 Bytes Maximum)

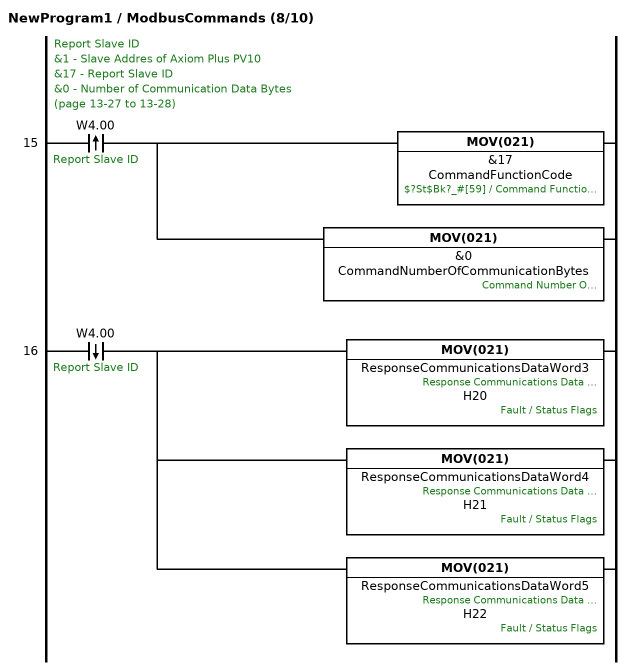
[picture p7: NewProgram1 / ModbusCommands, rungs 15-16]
; rung 15: Report Slave ID / &1 - Slave Addres of Axiom Plus PV10 / &17 - Report Slave ID / &0 - Number of Communication Data Bytes / (page 13-27 to 13-28)
@LD W4.00  ; Report Slave ID
MOV(021) &17 CommandFunctionCode  ; $?St$Bk?_#[59] / Command Function Code / Bits 0-7 (*8-15 = 00)$?St$Bk?_#[59]
MOV(021) &0 CommandNumberOfCommunicationBytes  ; Command Number Of Communications Data Bytes (0000 To 005E HEX)
; rung 16
%LD W4.00  ; Report Slave ID
MOV(021) ResponseCommunicationsDataWord3 H20  ; Response Communications Data - Word 3 (92 Bytes Maximum), Fault / Status Flags
MOV(021) ResponseCommunicationsDataWord4 H21  ; Response Communications Data - Word 4 (92 Bytes Maximum), Fault / Status Flags
MOV(021) ResponseCommunicationsDataWord5 H22  ; Response Communications Data - Word 5 (92 Bytes Maximum), Fault / Status Flags

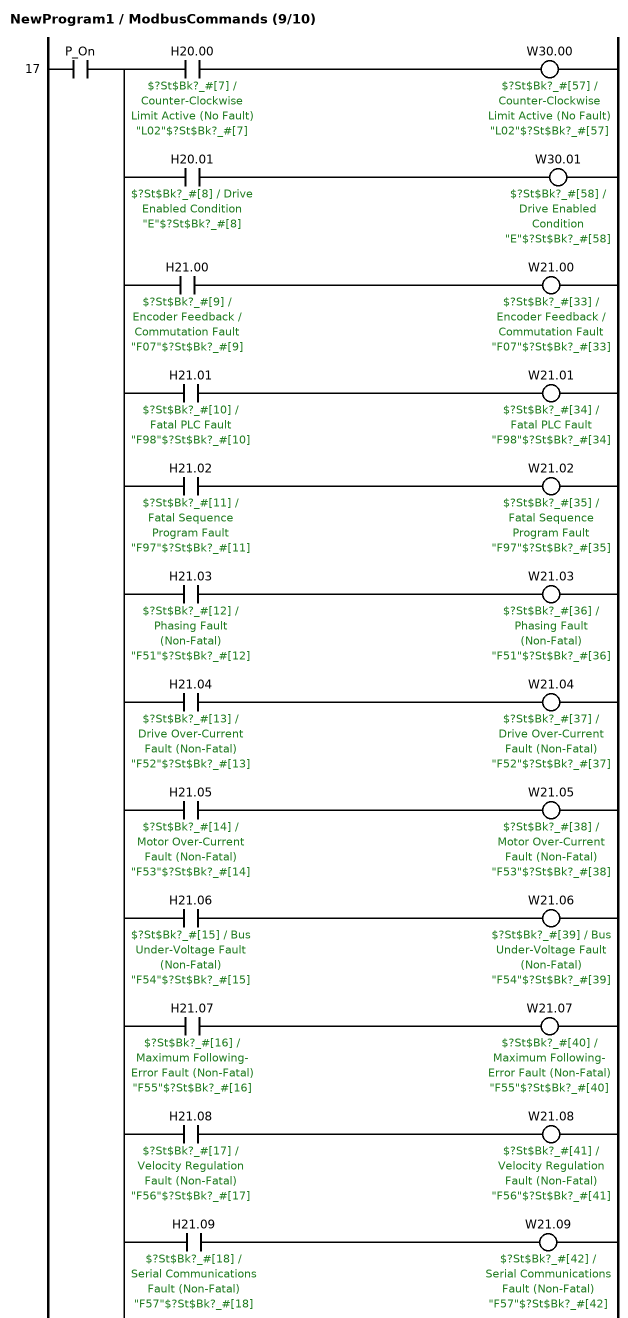
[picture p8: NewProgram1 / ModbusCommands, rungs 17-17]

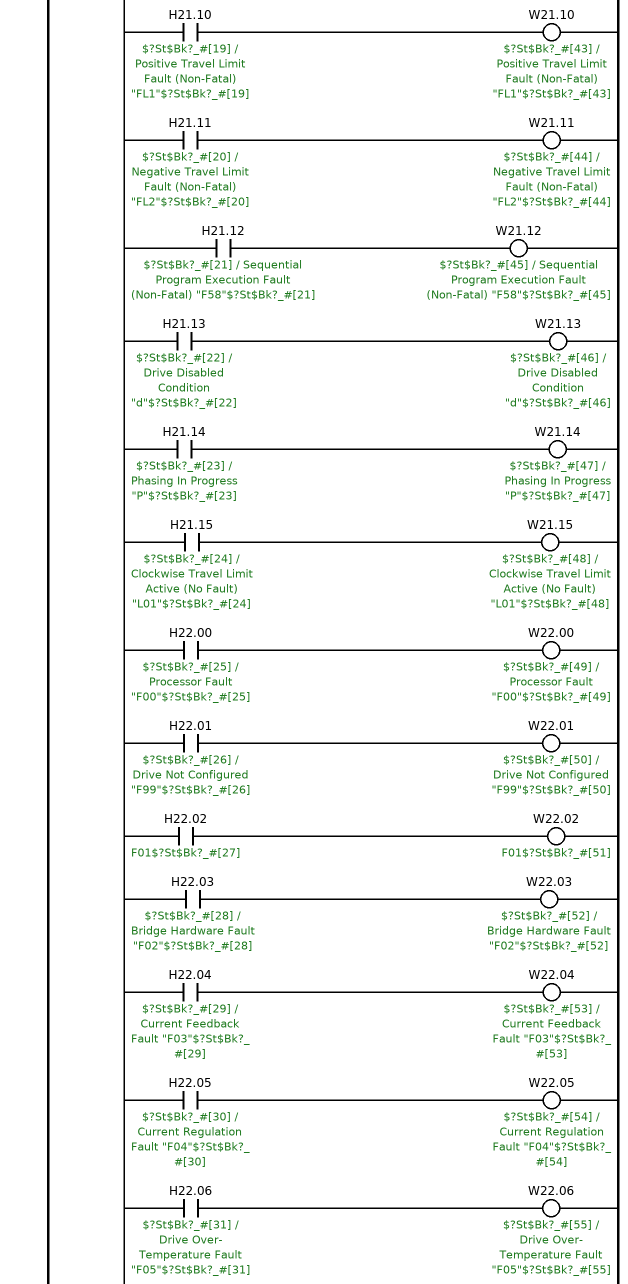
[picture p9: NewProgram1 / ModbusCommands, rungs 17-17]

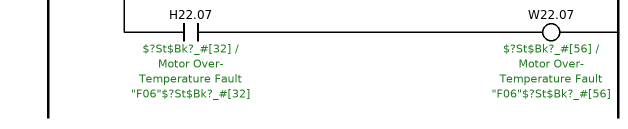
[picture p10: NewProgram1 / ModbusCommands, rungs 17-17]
; rung 17
LD P_On
OUT TR0
AND H20.00  ; $?St$Bk?_#[7] / Counter-Clockwise Limit Active (No Fault) "L02"$?St$Bk?_#[7]
OUT W30.00  ; $?St$Bk?_#[57] / Counter-Clockwise Limit Active (No Fault) "L02"$?St$Bk?_#[57]
LD TR0
AND H20.01  ; $?St$Bk?_#[8] / Drive Enabled Condition "E"$?St$Bk?_#[8]
OUT W30.01  ; $?St$Bk?_#[58] / Drive Enabled Condition "E"$?St$Bk?_#[58]
LD TR0
AND H21.00  ; $?St$Bk?_#[9] / Encoder Feedback / Commutation Fault "F07"$?St$Bk?_#[9]
OUT W21.00  ; $?St$Bk?_#[33] / Encoder Feedback / Commutation Fault "F07"$?St$Bk?_#[33]
LD TR0
AND H21.01  ; $?St$Bk?_#[10] / Fatal PLC Fault "F98"$?St$Bk?_#[10]
OUT W21.01  ; $?St$Bk?_#[34] / Fatal PLC Fault "F98"$?St$Bk?_#[34]
LD TR0
AND H21.02  ; $?St$Bk?_#[11] / Fatal Sequence Program Fault "F97"$?St$Bk?_#[11]
OUT W21.02  ; $?St$Bk?_#[35] / Fatal Sequence Program Fault "F97"$?St$Bk?_#[35]
LD TR0
AND H21.03  ; $?St$Bk?_#[12] / Phasing Fault (Non-Fatal) "F51"$?St$Bk?_#[12]
OUT W21.03  ; $?St$Bk?_#[36] / Phasing Fault (Non-Fatal) "F51"$?St$Bk?_#[36]
LD TR0
AND H21.04  ; $?St$Bk?_#[13] / Drive Over-Current Fault (Non-Fatal) "F52"$?St$Bk?_#[13]
OUT W21.04  ; $?St$Bk?_#[37] / Drive Over-Current Fault (Non-Fatal) "F52"$?St$Bk?_#[37]
LD TR0
AND H21.05  ; $?St$Bk?_#[14] / Motor Over-Current Fault (Non-Fatal) "F53"$?St$Bk?_#[14]
OUT W21.05  ; $?St$Bk?_#[38] / Motor Over-Current Fault (Non-Fatal) "F53"$?St$Bk?_#[38]
LD TR0
AND H21.06  ; $?St$Bk?_#[15] / Bus Under-Voltage Fault (Non-Fatal) "F54"$?St$Bk?_#[15]
OUT W21.06  ; $?St$Bk?_#[39] / Bus Under-Voltage Fault (Non-Fatal) "F54"$?St$Bk?_#[39]
LD TR0
AND H21.07  ; $?St$Bk?_#[16] / Maximum Following-Error Fault (Non-Fatal) "F55"$?St$Bk?_#[16]
OUT W21.07  ; $?St$Bk?_#[40] / Maximum Following-Error Fault (Non-Fatal) "F55"$?St$Bk?_#[40]
LD TR0
AND H21.08  ; $?St$Bk?_#[17] / Velocity Regulation Fault (Non-Fatal) "F56"$?St$Bk?_#[17]
OUT W21.08  ; $?St$Bk?_#[41] / Velocity Regulation Fault (Non-Fatal) "F56"$?St$Bk?_#[41]
LD TR0
AND H21.09  ; $?St$Bk?_#[18] / Serial Communications Fault (Non-Fatal) "F57"$?St$Bk?_#[18]
OUT W21.09  ; $?St$Bk?_#[42] / Serial Communications Fault (Non-Fatal) "F57"$?St$Bk?_#[42]
LD TR0
AND H21.10  ; $?St$Bk?_#[19] / Positive Travel Limit Fault (Non-Fatal) "FL1"$?St$Bk?_#[19]
OUT W21.10  ; $?St$Bk?_#[43] / Positive Travel Limit Fault (Non-Fatal) "FL1"$?St$Bk?_#[43]
LD TR0
AND H21.11  ; $?St$Bk?_#[20] / Negative Travel Limit Fault (Non-Fatal) "FL2"$?St$Bk?_#[20]
OUT W21.11  ; $?St$Bk?_#[44] / Negative Travel Limit Fault (Non-Fatal) "FL2"$?St$Bk?_#[44]
LD TR0
AND H21.12  ; $?St$Bk?_#[21] / Sequential Program Execution Fault (Non-Fatal) "F58"$?St$Bk?_#[21]
OUT W21.12  ; $?St$Bk?_#[45] / Sequential Program Execution Fault (Non-Fatal) "F58"$?St$Bk?_#[45]
LD TR0
AND H21.13  ; $?St$Bk?_#[22] / Drive Disabled Condition "d"$?St$Bk?_#[22]
OUT W21.13  ; $?St$Bk?_#[46] / Drive Disabled Condition "d"$?St$Bk?_#[46]
LD TR0
AND H21.14  ; $?St$Bk?_#[23] / Phasing In Progress "P"$?St$Bk?_#[23]
OUT W21.14  ; $?St$Bk?_#[47] / Phasing In Progress "P"$?St$Bk?_#[47]
LD TR0
AND H21.15  ; $?St$Bk?_#[24] / Clockwise Travel Limit Active (No Fault) "L01"$?St$Bk?_#[24]
OUT W21.15  ; $?St$Bk?_#[48] / Clockwise Travel Limit Active (No Fault) "L01"$?St$Bk?_#[48]
LD TR0
AND H22.00  ; $?St$Bk?_#[25] / Processor Fault "F00"$?St$Bk?_#[25]
OUT W22.00  ; $?St$Bk?_#[49] / Processor Fault "F00"$?St$Bk?_#[49]
LD TR0
AND H22.01  ; $?St$Bk?_#[26] / Drive Not Configured "F99"$?St$Bk?_#[26]
OUT W22.01  ; $?St$Bk?_#[50] / Drive Not Configured "F99"$?St$Bk?_#[50]
LD TR0
AND H22.02  ; F01$?St$Bk?_#[27]
OUT W22.02  ; F01$?St$Bk?_#[51]
LD TR0
AND H22.03  ; $?St$Bk?_#[28] / Bridge Hardware Fault "F02"$?St$Bk?_#[28]
OUT W22.03  ; $?St$Bk?_#[52] / Bridge Hardware Fault "F02"$?St$Bk?_#[52]
LD TR0
AND H22.04  ; $?St$Bk?_#[29] / Current Feedback Fault "F03"$?St$Bk?_#[29]
OUT W22.04  ; $?St$Bk?_#[53] / Current Feedback Fault "F03"$?St$Bk?_#[53]
LD TR0
AND H22.05  ; $?St$Bk?_#[30] / Current Regulation Fault "F04"$?St$Bk?_#[30]
OUT W22.05  ; $?St$Bk?_#[54] / Current Regulation Fault "F04"$?St$Bk?_#[54]
LD TR0
AND H22.06  ; $?St$Bk?_#[31] / Drive Over-Temperature Fault "F05"$?St$Bk?_#[31]
OUT W22.06  ; $?St$Bk?_#[55] / Drive Over-Temperature Fault "F05"$?St$Bk?_#[55]
LD TR0
AND H22.07  ; $?St$Bk?_#[32] / Motor Over-Temperature Fault "F06"$?St$Bk?_#[32]
OUT W22.07  ; $?St$Bk?_#[56] / Motor Over-Temperature Fault "F06"$?St$Bk?_#[56]

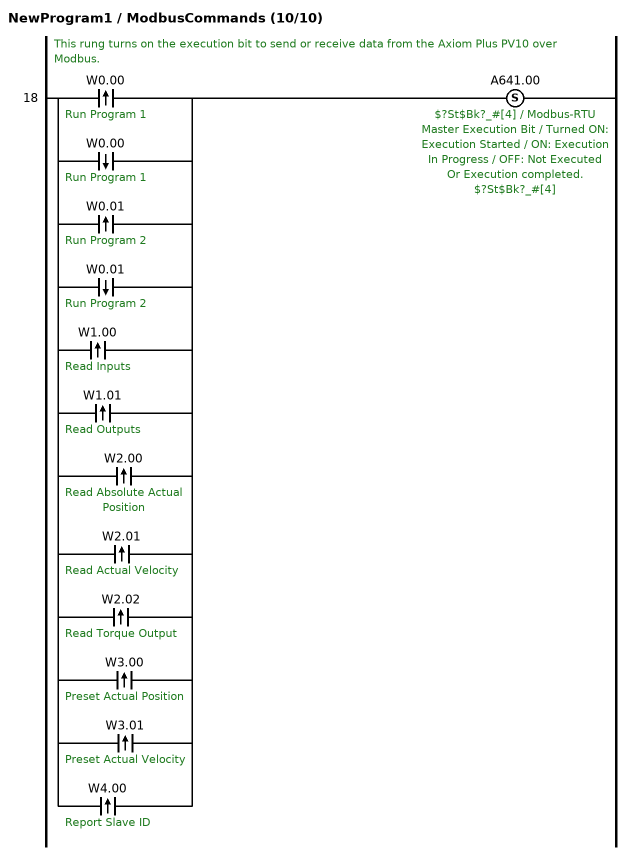
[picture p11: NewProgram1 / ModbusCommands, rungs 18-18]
; rung 18: This rung turns on the execution bit to send or receive data from the Axiom Plus PV10 over Modbus.
@LD W0.00  ; Run Program 1
%OR W0.00  ; Run Program 1
@OR W0.01  ; Run Program 2
%OR W0.01  ; Run Program 2
@OR W1.00  ; Read Inputs
@OR W1.01  ; Read Outputs
@OR W2.00  ; Read Absolute Actual Position
@OR W2.01  ; Read Actual Velocity
@OR W2.02  ; Read Torque Output
@OR W3.00  ; Preset Actual Position
@OR W3.01  ; Preset Actual Velocity
@OR W4.00  ; Report Slave ID
SET A641.00  ; $?St$Bk?_#[4] / Modbus-RTU Master Execution Bit / Turned ON: Execution Started / ON: Execution In Progress / OFF: Not Executed Or Execution completed.$?St$Bk?_#[4]

### Section END
; rung 0
END(001)

## Function block ForceSingleCoil
VAR_INPUT
  SlaveAddress : WORD;  (* $?St$Bk?_#[67] / Command Slave Address (00 To F7 HEX) / Bits 0-7 (*8-15 = 00)$?St$Bk?_#[67] *)
  PLC_ForcingFlag : INT;
  On_Off : WORD;
END_VAR
VAR_OUTPUT
  CommandSlaveAddress : WORD;  (* $?St$Bk?_#[68] / Command Slave Address (00 To F7 HEX) / Bits 0-7 (*8-15 = 00)$?St$Bk?_#[68] *)
  CommandFunctionCode : WORD;  (* $?St$Bk?_#[69] / Command Function Code / Bits 0-7 (*8-15 = 00)$?St$Bk?_#[69] *)
  CommandNumberOfCommunicationBytes : WORD;  (* Command Number Of Communications Data Bytes (0000 To 005E HEX) *)
  CommandCommunicationsDataWord1 : WORD;  (* Command Communications Data - Word 1 (94 Bytes Maximum) *)
  CommandCommunicationsDataWord2 : WORD;  (* Command Communications Data - Word 2 (94 Bytes Maximum) *)
END_VAR

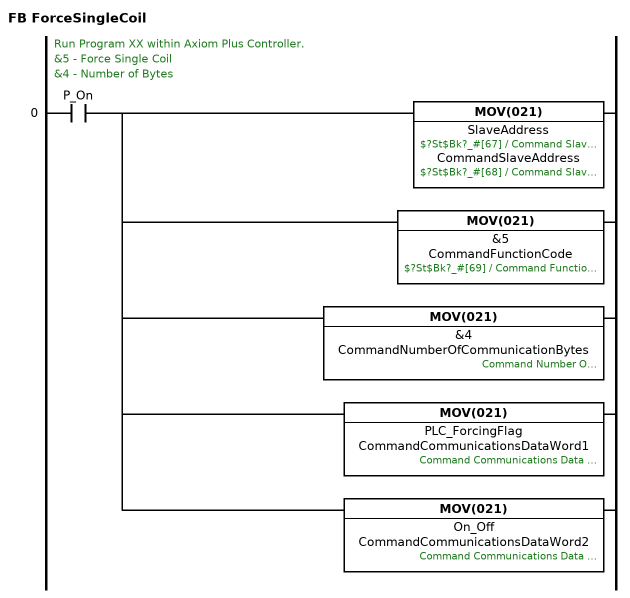
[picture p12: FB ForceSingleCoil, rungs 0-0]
; rung 0: Run Program XX within Axiom Plus Controller. / &5 - Force Single Coil / &4 - Number of Bytes
LD P_On
MOV(021) SlaveAddress CommandSlaveAddress  ; $?St$Bk?_#[67] / Command Slave Address (00 To F7 HEX) / Bits 0-7 (*8-15 = 00)$?St$Bk?_#[67], $?St$Bk?_#[68] / Command Slave Address (00 To F7 HEX) / Bits 0-7 (*8-15 = 00)$?St$Bk?_#[68]
MOV(021) &5 CommandFunctionCode  ; $?St$Bk?_#[69] / Command Function Code / Bits 0-7 (*8-15 = 00)$?St$Bk?_#[69]
MOV(021) &4 CommandNumberOfCommunicationBytes  ; Command Number Of Communications Data Bytes (0000 To 005E HEX)
MOV(021) PLC_ForcingFlag CommandCommunicationsDataWord1  ; Command Communications Data - Word 1 (94 Bytes Maximum)
MOV(021) On_Off CommandCommunicationsDataWord2  ; Command Communications Data - Word 2 (94 Bytes Maximum)

## Function block PresetRegister
VAR_INPUT
  SlaveAddress : WORD;  (* $?St$Bk?_#[72] / Command Slave Address (00 To F7 HEX) / Bits 0-7 (*8-15 = 00)$?St$Bk?_#[72] *)
  PresetRegister : INT;
  RAM_RegisterValue : DINT;  (* RAM Register Value *)
END_VAR
VAR_OUTPUT
  CommandSlaveAddress : WORD;  (* $?St$Bk?_#[73] / Command Slave Address (00 To F7 HEX) / Bits 0-7 (*8-15 = 00)$?St$Bk?_#[73] *)
  CommandFunctionCode : WORD;  (* $?St$Bk?_#[74] / Command Function Code / Bits 0-7 (*8-15 = 00)$?St$Bk?_#[74] *)
  CommandNumberOfCommunicationBytes : WORD;  (* Command Number Of Communications Data Bytes (0000 To 005E HEX) *)
  CommandCommunicationsDataWord1 : WORD;  (* Command Communications Data - Word 1 (94 Bytes Maximum) *)
  CommandCommunicationsDataWord2 : WORD;  (* Command Communications Data - Word 2 (94 Bytes Maximum) *)
  CommandCommunicationsDataWord3 : WORD;  (* Command Communications Data - Word 3 (94 Bytes Maximum) *)
  CommandCommunicationsDataWord4 : WORD;  (* Command Communications Data - Word 4 (94 Bytes Maximum) *)
  CommandCommunicationsDataWord5 : WORD;  (* Command Communications Data - Word 5 (94 Bytes Maximum) *)
END_VAR
VAR
  NumberOfModbusDataBytes : WORD;  (* Number Of Modbus Data Bytes *)
  RAM_RegisterTemporary : DINT;
END_VAR

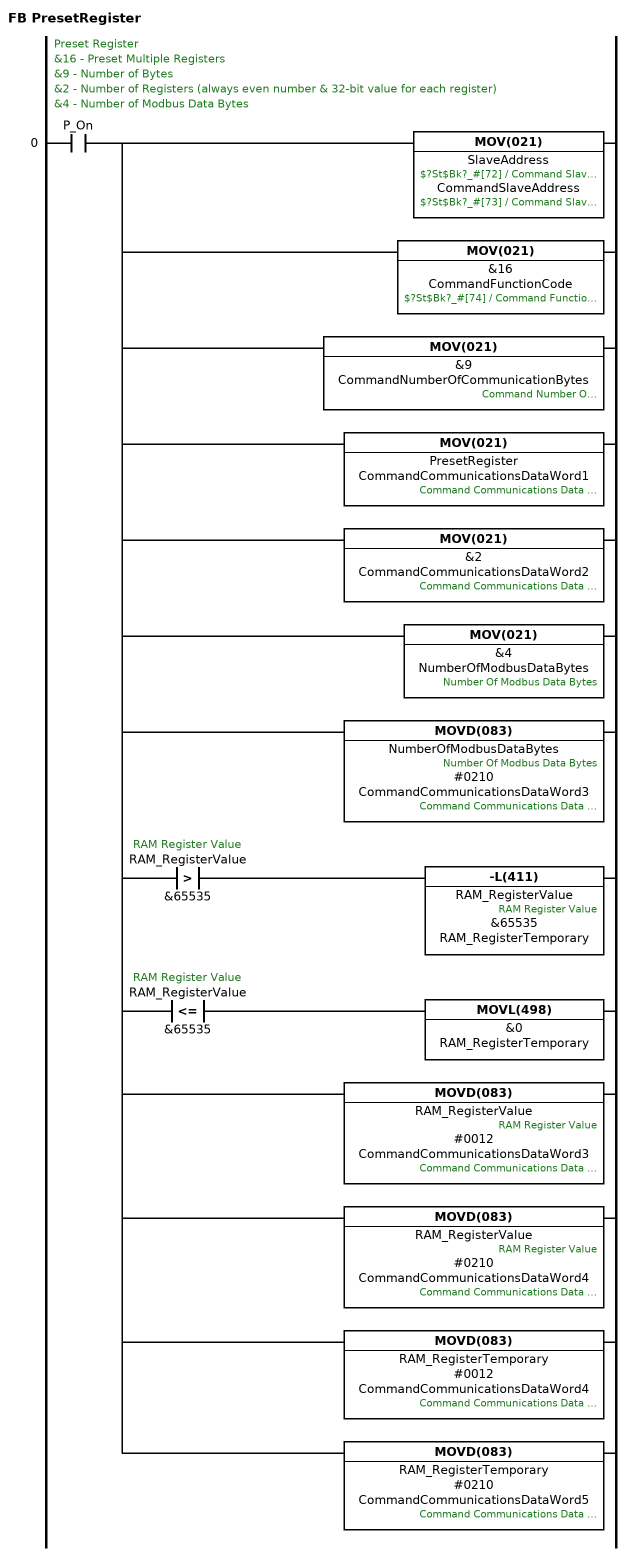
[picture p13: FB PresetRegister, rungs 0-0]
; rung 0: Preset Register / &16 - Preset Multiple Registers / &9 - Number of Bytes / &2 - Number of Registers (always even number & 32-bit value for each register) / &4 - Number of Modbus Data Bytes
LD P_On
OUT TR0
MOV(021) SlaveAddress CommandSlaveAddress  ; $?St$Bk?_#[72] / Command Slave Address (00 To F7 HEX) / Bits 0-7 (*8-15 = 00)$?St$Bk?_#[72], $?St$Bk?_#[73] / Command Slave Address (00 To F7 HEX) / Bits 0-7 (*8-15 = 00)$?St$Bk?_#[73]
MOV(021) &16 CommandFunctionCode  ; $?St$Bk?_#[74] / Command Function Code / Bits 0-7 (*8-15 = 00)$?St$Bk?_#[74]
MOV(021) &9 CommandNumberOfCommunicationBytes  ; Command Number Of Communications Data Bytes (0000 To 005E HEX)
MOV(021) PresetRegister CommandCommunicationsDataWord1  ; Command Communications Data - Word 1 (94 Bytes Maximum)
MOV(021) &2 CommandCommunicationsDataWord2  ; Command Communications Data - Word 2 (94 Bytes Maximum)
MOV(021) &4 NumberOfModbusDataBytes  ; Number Of Modbus Data Bytes
MOVD(083) NumberOfModbusDataBytes #0210 CommandCommunicationsDataWord3  ; Number Of Modbus Data Bytes, Command Communications Data - Word 3 (94 Bytes Maximum)
AND>SL(323) RAM_RegisterValue &65535  ; RAM Register Value
-L(411) RAM_RegisterValue &65535 RAM_RegisterTemporary  ; RAM Register Value
LD TR0
AND<=SL(318) RAM_RegisterValue &65535  ; RAM Register Value
MOVL(498) &0 RAM_RegisterTemporary
LD TR0
MOVD(083) RAM_RegisterValue #0012 CommandCommunicationsDataWord3  ; RAM Register Value, Command Communications Data - Word 3 (94 Bytes Maximum)
MOVD(083) RAM_RegisterValue #0210 CommandCommunicationsDataWord4  ; RAM Register Value, Command Communications Data - Word 4 (94 Bytes Maximum)
MOVD(083) RAM_RegisterTemporary #0012 CommandCommunicationsDataWord4  ; Command Communications Data - Word 4 (94 Bytes Maximum)
MOVD(083) RAM_RegisterTemporary #0210 CommandCommunicationsDataWord5  ; Command Communications Data - Word 5 (94 Bytes Maximum)

## Function block ReadHoldingRegister
VAR_INPUT
  SlaveAddress : WORD;  (* $?St$Bk?_#[77] / Command Slave Address (00 To F7 HEX) / Bits 0-7 (*8-15 = 00)$?St$Bk?_#[77] *)
  ReadHoldingRegister : INT;
  ResponseCommunicationsDataWord1 : WORD;  (* Response Communications Data - Word 1 (92 Bytes Maximum) *)
  ResponseCommunicationsDataWord2 : WORD;  (* Response Communications Data - Word 2 (92 Bytes Maximum) *)
  ResponseCommunicationsDataWord3 : WORD;  (* Response Communications Data - Word 3 (92 Bytes Maximum) *)
END_VAR
VAR_OUTPUT
  CommandSlaveAddress : WORD;  (* $?St$Bk?_#[78] / Command Slave Address (00 To F7 HEX) / Bits 0-7 (*8-15 = 00)$?St$Bk?_#[78] *)
  CommandFunctionCode : WORD;  (* $?St$Bk?_#[79] / Command Function Code / Bits 0-7 (*8-15 = 00)$?St$Bk?_#[79] *)
  CommandNumberOfCommunicationBytes : WORD;  (* Command Number Of Communications Data Bytes (0000 To 005E HEX) *)
  CommandCommunicationsDataWord1 : WORD;  (* Command Communications Data - Word 1 (94 Bytes Maximum) *)
  CommandCommunicationsDataWord2 : WORD;  (* Command Communications Data - Word 2 (94 Bytes Maximum) *)
  AbsoluteActualPosition : DINT;
END_VAR
VAR
  AbsoluteActualPositionLSW : DINT;  (* Absolute Actual Position *)
  AbsoluteActualPositionMSW : DINT;  (* Absolute Actual Position *)
  AbsoluteActualPositionTemporary : DINT;
END_VAR

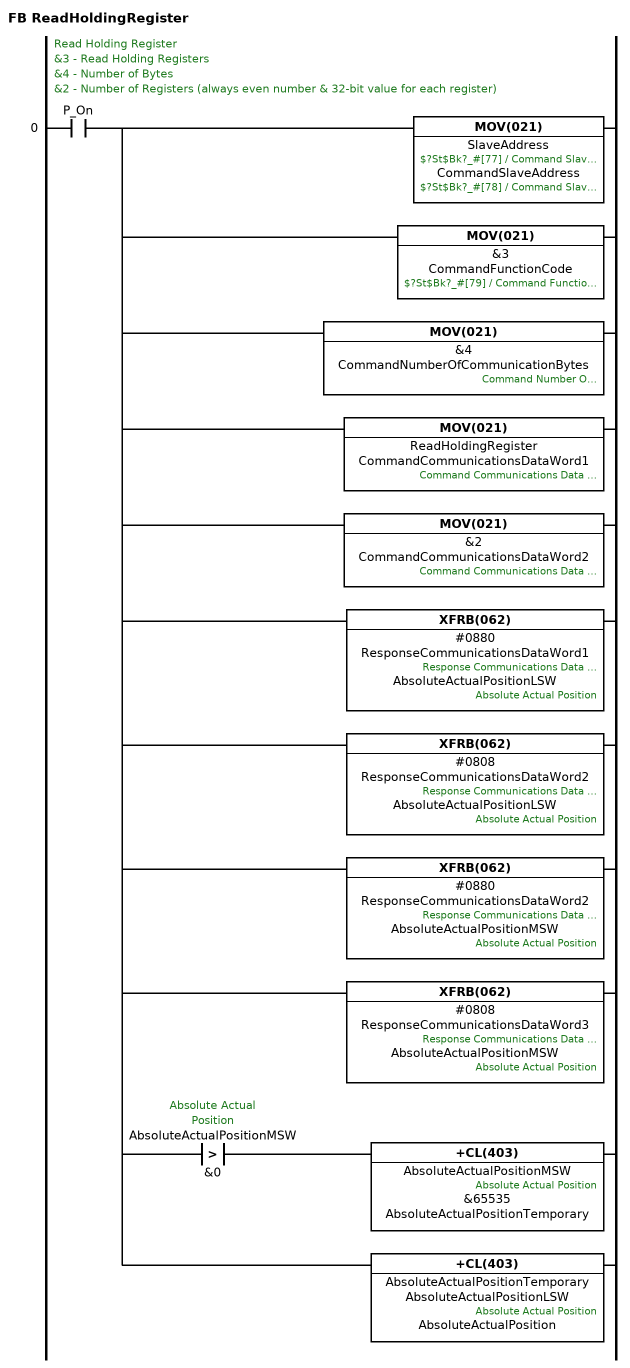
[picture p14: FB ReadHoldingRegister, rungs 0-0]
; rung 0: Read Holding Register / &3 - Read Holding Registers / &4 - Number of Bytes / &2 - Number of Registers (always even number & 32-bit value for each register)
LD P_On
OUT TR0
MOV(021) SlaveAddress CommandSlaveAddress  ; $?St$Bk?_#[77] / Command Slave Address (00 To F7 HEX) / Bits 0-7 (*8-15 = 00)$?St$Bk?_#[77], $?St$Bk?_#[78] / Command Slave Address (00 To F7 HEX) / Bits 0-7 (*8-15 = 00)$?St$Bk?_#[78]
MOV(021) &3 CommandFunctionCode  ; $?St$Bk?_#[79] / Command Function Code / Bits 0-7 (*8-15 = 00)$?St$Bk?_#[79]
MOV(021) &4 CommandNumberOfCommunicationBytes  ; Command Number Of Communications Data Bytes (0000 To 005E HEX)
MOV(021) ReadHoldingRegister CommandCommunicationsDataWord1  ; Command Communications Data - Word 1 (94 Bytes Maximum)
MOV(021) &2 CommandCommunicationsDataWord2  ; Command Communications Data - Word 2 (94 Bytes Maximum)
XFRB(062) #0880 ResponseCommunicationsDataWord1 AbsoluteActualPositionLSW  ; Response Communications Data - Word 1 (92 Bytes Maximum), Absolute Actual Position
XFRB(062) #0808 ResponseCommunicationsDataWord2 AbsoluteActualPositionLSW  ; Response Communications Data - Word 2 (92 Bytes Maximum), Absolute Actual Position
XFRB(062) #0880 ResponseCommunicationsDataWord2 AbsoluteActualPositionMSW  ; Response Communications Data - Word 2 (92 Bytes Maximum), Absolute Actual Position
XFRB(062) #0808 ResponseCommunicationsDataWord3 AbsoluteActualPositionMSW  ; Response Communications Data - Word 3 (92 Bytes Maximum), Absolute Actual Position
AND>S(322) AbsoluteActualPositionMSW &0  ; Absolute Actual Position
+CL(403) AbsoluteActualPositionMSW &65535 AbsoluteActualPositionTemporary  ; Absolute Actual Position
LD TR0
+CL(403) AbsoluteActualPositionTemporary AbsoluteActualPositionLSW AbsoluteActualPosition  ; Absolute Actual Position

## Function block ReadInputStatus
VAR_INPUT
  SlaveAddress : WORD;  (* $?St$Bk?_#[82] / Command Slave Address (00 To F7 HEX) / Bits 0-7 (*8-15 = 00)$?St$Bk?_#[82] *)
  StartingAddress : INT;
  NumberOfConsecutiveInputs : INT;
END_VAR
VAR_OUTPUT
  CommandSlaveAddress : WORD;  (* $?St$Bk?_#[83] / Command Slave Address (00 To F7 HEX) / Bits 0-7 (*8-15 = 00)$?St$Bk?_#[83] *)
  CommandFunctionCode : WORD;  (* $?St$Bk?_#[84] / Command Function Code / Bits 0-7 (*8-15 = 00)$?St$Bk?_#[84] *)
  CommandNumberOfCommunicationBytes : WORD;  (* Command Number Of Communications Data Bytes (0000 To 005E HEX) *)
  CommandCommunicationsDataWord1 : WORD;  (* Command Communications Data - Word 1 (94 Bytes Maximum) *)
  CommandCommunicationsDataWord2 : WORD;  (* Command Communications Data - Word 2 (94 Bytes Maximum) *)
END_VAR

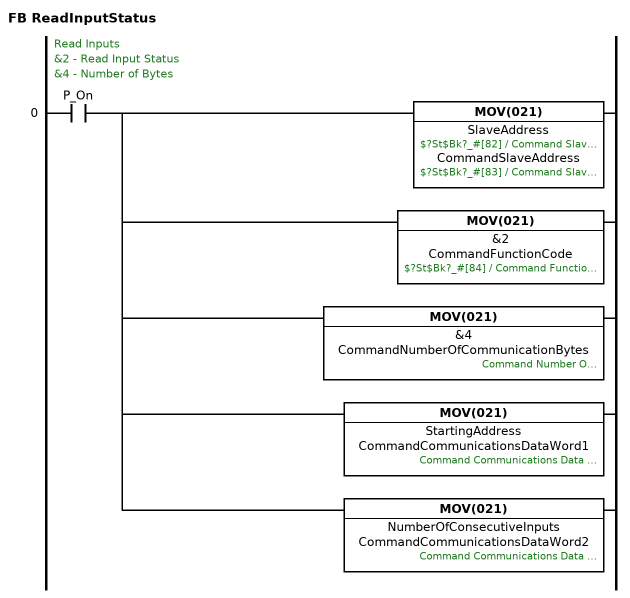
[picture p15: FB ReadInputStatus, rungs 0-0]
; rung 0: Read Inputs / &2 - Read Input Status / &4 - Number of Bytes
LD P_On
MOV(021) SlaveAddress CommandSlaveAddress  ; $?St$Bk?_#[82] / Command Slave Address (00 To F7 HEX) / Bits 0-7 (*8-15 = 00)$?St$Bk?_#[82], $?St$Bk?_#[83] / Command Slave Address (00 To F7 HEX) / Bits 0-7 (*8-15 = 00)$?St$Bk?_#[83]
MOV(021) &2 CommandFunctionCode  ; $?St$Bk?_#[84] / Command Function Code / Bits 0-7 (*8-15 = 00)$?St$Bk?_#[84]
MOV(021) &4 CommandNumberOfCommunicationBytes  ; Command Number Of Communications Data Bytes (0000 To 005E HEX)
MOV(021) StartingAddress CommandCommunicationsDataWord1  ; Command Communications Data - Word 1 (94 Bytes Maximum)
MOV(021) NumberOfConsecutiveInputs CommandCommunicationsDataWord2  ; Command Communications Data - Word 2 (94 Bytes Maximum)

## Function block ReadOutputStatus
VAR_INPUT
  SlaveAddress : WORD;  (* $?St$Bk?_#[87] / Command Slave Address (00 To F7 HEX) / Bits 0-7 (*8-15 = 00)$?St$Bk?_#[87] *)
  StartingAddress : INT;
  NumberOfConsecutiveOutputs : INT;
END_VAR
VAR_OUTPUT
  CommandSlaveAddress : WORD;  (* $?St$Bk?_#[88] / Command Slave Address (00 To F7 HEX) / Bits 0-7 (*8-15 = 00)$?St$Bk?_#[88] *)
  CommandFunctionCode : WORD;  (* $?St$Bk?_#[89] / Command Function Code / Bits 0-7 (*8-15 = 00)$?St$Bk?_#[89] *)
  CommandNumberOfCommunicationBytes : WORD;  (* Command Number Of Communications Data Bytes (0000 To 005E HEX) *)
  CommandCommunicationsDataWord1 : WORD;  (* Command Communications Data - Word 1 (94 Bytes Maximum) *)
  CommandCommunicationsDataWord2 : WORD;  (* Command Communications Data - Word 2 (94 Bytes Maximum) *)
END_VAR

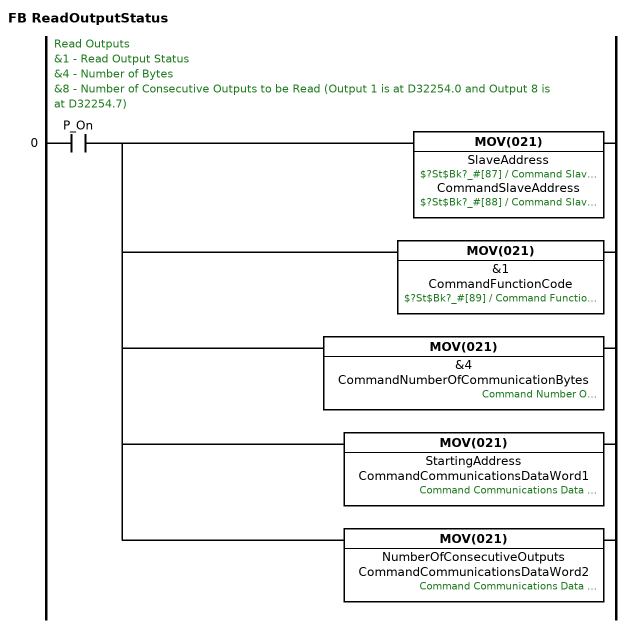
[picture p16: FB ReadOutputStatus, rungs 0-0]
; rung 0: Read Outputs / &1 - Read Output Status / &4 - Number of Bytes / &8 - Number of Consecutive Outputs to be Read (Output 1 is at D32254.0 and Output 8 is at D32254.7)
LD P_On
MOV(021) SlaveAddress CommandSlaveAddress  ; $?St$Bk?_#[87] / Command Slave Address (00 To F7 HEX) / Bits 0-7 (*8-15 = 00)$?St$Bk?_#[87], $?St$Bk?_#[88] / Command Slave Address (00 To F7 HEX) / Bits 0-7 (*8-15 = 00)$?St$Bk?_#[88]
MOV(021) &1 CommandFunctionCode  ; $?St$Bk?_#[89] / Command Function Code / Bits 0-7 (*8-15 = 00)$?St$Bk?_#[89]
MOV(021) &4 CommandNumberOfCommunicationBytes  ; Command Number Of Communications Data Bytes (0000 To 005E HEX)
MOV(021) StartingAddress CommandCommunicationsDataWord1  ; Command Communications Data - Word 1 (94 Bytes Maximum)
MOV(021) NumberOfConsecutiveOutputs CommandCommunicationsDataWord2  ; Command Communications Data - Word 2 (94 Bytes Maximum)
